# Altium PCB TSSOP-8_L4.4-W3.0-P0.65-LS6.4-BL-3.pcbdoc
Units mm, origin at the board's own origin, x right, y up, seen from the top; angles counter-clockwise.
Board outline 16.14 x 20.6 mm, 2 copper layers (Top Layer, Bottom Layer), stack 0 mm thick; 1 components, 0 nets, 8 pads, 0 vias.
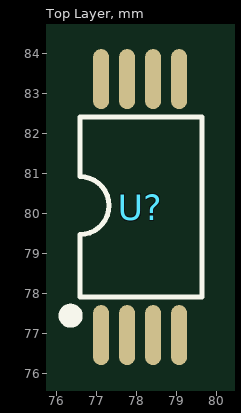
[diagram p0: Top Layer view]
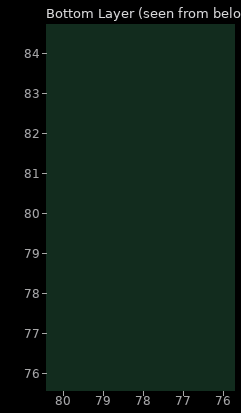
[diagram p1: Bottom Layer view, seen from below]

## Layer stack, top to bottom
Top Layer: signal copper (thickness not stored)
Bottom Layer: signal copper (thickness not stored)

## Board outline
85.986,69.85 69.85,69.85 69.85,90.451 85.986,90.451

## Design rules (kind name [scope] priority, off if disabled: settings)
PasteMaskExpansion "Paste Mask Expansion" [All] p1: expansion=0
SolderMaskExpansion "Solder Mask Expansion" [IsVia] p1: expansion=-25.4 istentingtop=TRUE
SolderMaskExpansion "Solder Mask Expansion" [All] p2: expansion=0.051 istentingtop=FALSE

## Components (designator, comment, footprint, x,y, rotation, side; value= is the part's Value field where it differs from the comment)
U? "" TSSOP-8_L4.4-W3.0-P0.65-LS6.4-BL-3 78.086,80.15 r0 top

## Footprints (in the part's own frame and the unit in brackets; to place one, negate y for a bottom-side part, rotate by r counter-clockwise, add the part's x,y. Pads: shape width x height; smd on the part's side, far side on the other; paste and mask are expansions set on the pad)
TSSOP-8_L4.4-W3.0-P0.65-LS6.4-BL-3 [mm]
  oval 0.4x1.5 smd: 1(-0.975,-3.2) 2(-0.325,-3.2) 3(0.325,-3.2) 4(0.975,-3.2) 5(0.975,3.2) 6(0.325,3.2) 7(-0.325,3.2) 8(-0.975,3.2)
  silkscreen extent -1.89,-2.87 1.55,2.25

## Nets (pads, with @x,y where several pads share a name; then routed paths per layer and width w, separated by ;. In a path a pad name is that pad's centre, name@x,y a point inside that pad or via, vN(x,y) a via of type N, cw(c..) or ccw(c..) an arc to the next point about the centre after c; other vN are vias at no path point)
pads on no net: U?.1 U?.2 U?.3 U?.4 U?.5 U?.6 U?.7 U?.8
